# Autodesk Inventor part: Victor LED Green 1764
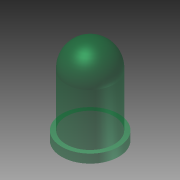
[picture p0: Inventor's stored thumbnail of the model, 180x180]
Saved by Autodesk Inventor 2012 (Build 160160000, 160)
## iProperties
Shininess: 64.0
Length Units: 11272
Angle Units: 11279
Time Units: 11290
Mass Units: 11286
Length Display Precision: 3
Angle Display Precision: 2
Compacted: True
Part Number: Victor LED Green 1764
Document SubType Name: Modeling
Created: 2005-12
Designer: Owner
Material: ABS Plastic
Density: 1 g/cm^3
Density: 0.0
Volumn: 0.0
Area: 0.0
PropertySet Name: Model Information
Control State: 0
Master: False
Checked Out: False
Author: Owner
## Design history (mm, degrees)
sketch "Sketch1"
  geometry: L1 (0, 0)-(0, 9); L2 (-2.491, 6.277)-(-2.491, 0.9); L3 (-2.491, 0.9)-(-2.95, 0.9); L4 (-2.95, 0.9)-(-2.95, 0); L5 (-2.95, 0)-(0, 0); A1 r 2.5 centre (-0.001, 6.5) between (0, 9) and (-2.491, 6.277)
  constraints: 10 end point, 3 parallel, 2 point on circle, 1 centre point, 1 perpendicular, 1 vertical, 1 other
  dimensions: "d0" = 5 diameter of A1; "d1" = 9 distance of L1.start L1.end; "d2" = 0.9 distance of L3.end L4.end; "d3" = 2.95 distance of L4.end L1.start
revolve "Revolution1" sketch "Sketch1" stored, may be unused: angle "d4" = 90 deg
body "Solid1"
